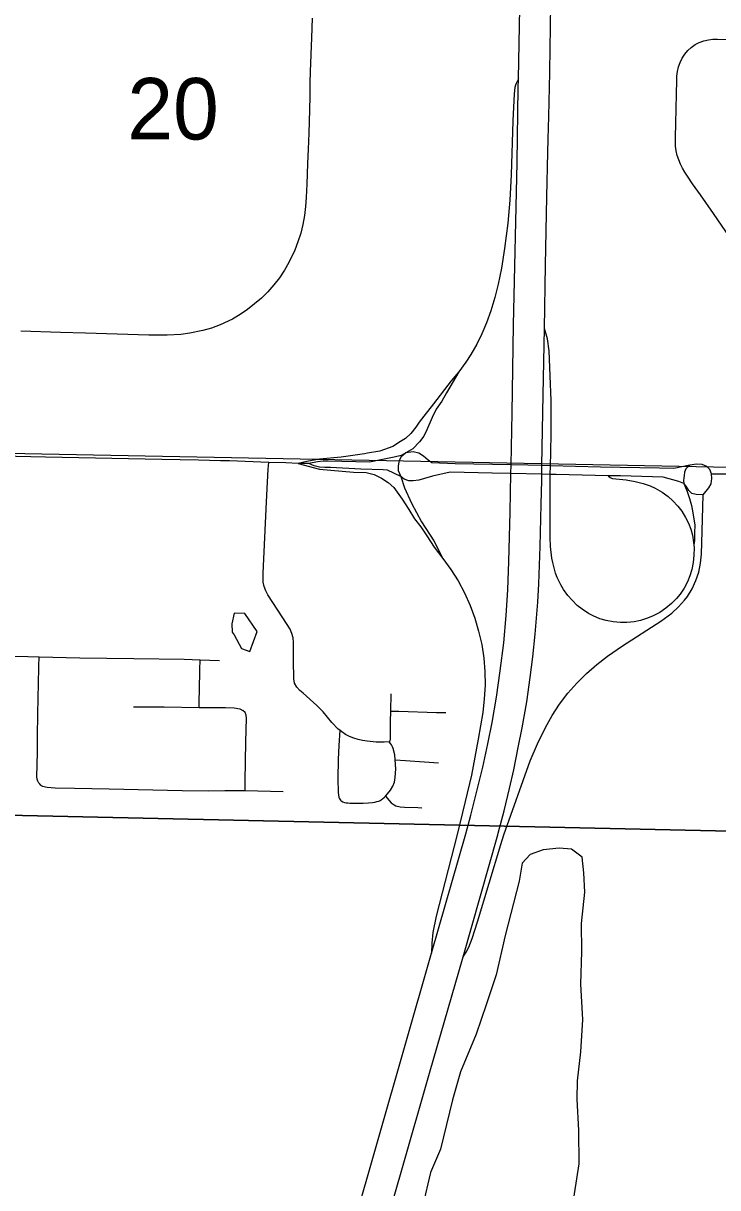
# Model space of a CAD drawing. Extents: x -59 to 43, y 0 to 22.
# Drawn here: x 26.628 to 27.1, y 17.014 to 17.807 of the extents above; entities that cross this region are included whole.
import ezdxf

# ---------------------------------------------------------------- set-up
doc = ezdxf.new("R2010")
doc.units = 0
for name, color, linetype in [('GM_X_City_Street', 7, 'Continuous'), ('GM_X_Interchange_Ramps', 7, 'Continuous'), ('GM_X_Interstate_Route', 7, 'Continuous'), ('GM_X_Minor_Lake', 7, 'Continuous'), ('GM_X_Rail_Line', 7, 'Continuous'), ('GM_X_Section', 7, 'Continuous'), ('GM_X_Section_Text', 7, 'Continuous'), ('GM_X_State_Route', 7, 'Continuous')]:
    doc.layers.add(name, color=color, linetype=linetype)

msp = doc.modelspace()

# ---------------------------------------------------------------- linework, layer by layer
at = {"layer": 'GM_X_City_Street'}
for p, q in [((26.87769, 17.33833), (26.87805, 17.34998)), ((26.77859, 17.28417), (26.80446, 17.28367))]:
    msp.add_line(p, q, dxfattribs=at)
for points in [[(26.82421, 17.81002), (26.82372, 17.79665), (26.82277, 17.77381), (26.82252, 17.76594), (26.82253, 17.75705), (26.82236, 17.74775), (26.82205, 17.73178), (26.82157, 17.72084), (26.82109, 17.71112), (26.82049, 17.69712), (26.82007, 17.68789), (26.81966, 17.68178), (26.81895, 17.67571), (26.81786, 17.66968), (26.8164, 17.66371), (26.81456, 17.65784), (26.81235, 17.65209), (26.80844, 17.64374), (26.80539, 17.63841), (26.80195, 17.6333), (26.7982, 17.62843), (26.79413, 17.62384), (26.78975, 17.61954), (26.78505, 17.61556), (26.78025, 17.61173), (26.77518, 17.60827), (26.76987, 17.60517), (26.76155, 17.6012), (26.75579, 17.59906), (26.74989, 17.59738), (26.74083, 17.59553), (26.73473, 17.59475), (26.7255, 17.59423), (26.71313, 17.59429), (26.66984, 17.59565), (26.65279, 17.59606), (26.62592, 17.59703)], [(27.12023, 17.64387), (27.09742, 17.67705), (27.08852, 17.68974), (27.08323, 17.69737), (27.07967, 17.70248), (27.07799, 17.70513), (27.07643, 17.70787), (27.07503, 17.71069), (27.07381, 17.7136), (27.07277, 17.7166), (27.07205, 17.71972), (27.07167, 17.72289), (27.07156, 17.72915), (27.07177, 17.73848), (27.07231, 17.75824), (27.07239, 17.76755), (27.07258, 17.77069), (27.073, 17.77383), (27.07372, 17.77694), (27.0748, 17.77995), (27.0762, 17.78282), (27.07791, 17.78553), (27.07994, 17.78802), (27.08229, 17.79021), (27.08493, 17.79206), (27.08778, 17.79353), (27.0908, 17.79465), (27.09393, 17.79536), (27.09708, 17.79572), (27.10022, 17.79584), (27.11882, 17.79547)], [(26.84297, 17.32526), (26.84197, 17.3261), (26.83771, 17.33061), (26.83168, 17.3377), (26.8274, 17.34218), (26.81815, 17.35045), (26.81592, 17.35236), (26.81374, 17.35454), (26.81226, 17.35723), (26.8117, 17.36025), (26.81152, 17.37267), (26.81146, 17.38508), (26.8112, 17.38817), (26.81046, 17.39116), (26.80921, 17.39398), (26.80427, 17.40187), (26.79411, 17.41747), (26.7926, 17.42019), (26.79149, 17.42307), (26.79096, 17.4261), (26.79088, 17.43231), (26.79311, 17.48072), (26.79385, 17.49426), (26.79435, 17.50299), (26.79477, 17.50758)], [(26.58492, 17.37613), (26.59661, 17.37603), (26.63063, 17.37539), (26.63829, 17.37522), (26.66608, 17.37458), (26.70277, 17.37405), (26.73697, 17.37363), (26.74792, 17.37324), (26.7612, 17.37277)], [(26.63811, 17.28919), (26.63745, 17.2905), (26.63701, 17.29206), (26.63686, 17.29357), (26.63713, 17.31038), (26.63731, 17.32096), (26.63739, 17.33654), (26.63819, 17.36769), (26.63821, 17.36893), (26.63829, 17.37522)], [(26.74728, 17.34081), (26.74739, 17.34562), (26.74756, 17.35245), (26.7478, 17.36643), (26.74792, 17.37324)], [(26.70251, 17.34121), (26.70917, 17.34117), (26.72355, 17.34125), (26.74728, 17.34081)], [(26.74728, 17.34081), (26.75566, 17.34066), (26.76533, 17.34069), (26.77117, 17.34045), (26.77488, 17.3398), (26.7771, 17.33865)], [(26.77859, 17.28417), (26.77869, 17.29065), (26.77908, 17.3174), (26.77943, 17.33355), (26.77924, 17.33544), (26.77858, 17.33725), (26.7771, 17.33865)], [(26.87663, 17.3174), (26.87725, 17.31815), (26.87763, 17.3192), (26.87748, 17.33132), (26.87769, 17.33833)], [(26.87769, 17.33833), (26.88323, 17.33816), (26.90879, 17.33742), (26.91519, 17.33739)], [(26.84297, 17.32526), (26.8424, 17.31486), (26.84189, 17.30529), (26.84166, 17.29244), (26.84198, 17.28287), (26.84217, 17.28122), (26.8424, 17.27977), (26.84267, 17.27902), (26.84297, 17.27826), (26.84344, 17.27759), (26.84392, 17.27711)], [(26.87663, 17.3174), (26.87331, 17.31708), (26.8677, 17.31721), (26.86165, 17.31787), (26.85859, 17.31836), (26.85557, 17.31906), (26.8526, 17.31995), (26.84969, 17.32103), (26.84692, 17.3224), (26.84434, 17.3241), (26.84297, 17.32526)], [(26.88082, 17.30511), (26.88044, 17.30845), (26.87943, 17.31274), (26.87901, 17.31397), (26.87822, 17.31538), (26.87753, 17.31635), (26.87663, 17.3174)], [(26.87423, 17.28048), (26.87561, 17.282), (26.87747, 17.28447), (26.87911, 17.2871), (26.8803, 17.28995), (26.88081, 17.29299), (26.88126, 17.29899), (26.88082, 17.30511)], [(26.88082, 17.30511), (26.88784, 17.30461), (26.91022, 17.30301)], [(26.63811, 17.28919), (26.63926, 17.28787), (26.64071, 17.28709), (26.64375, 17.28646), (26.64931, 17.28609), (26.66235, 17.28584), (26.68597, 17.28542), (26.71578, 17.28472), (26.73566, 17.28425), (26.75368, 17.28409), (26.76487, 17.28419), (26.77667, 17.2842), (26.77859, 17.28417)], [(26.84392, 17.27711), (26.84502, 17.27647), (26.84617, 17.27616), (26.84739, 17.2759), (26.84841, 17.27577), (26.84981, 17.2757), (26.859, 17.27572), (26.86246, 17.27587), (26.86519, 17.27613), (26.86687, 17.27641), (26.86823, 17.27669), (26.86953, 17.27704), (26.87043, 17.27743), (26.87108, 17.27784), (26.87243, 17.27882), (26.87353, 17.2797), (26.87423, 17.28048)], [(26.87423, 17.28048), (26.87668, 17.27753), (26.87811, 17.27578), (26.87994, 17.27453), (26.88117, 17.27387), (26.88406, 17.2732), (26.88704, 17.27291), (26.89608, 17.27274), (26.89897, 17.27251)]]:
    msp.add_lwpolyline(points, dxfattribs=at)
at = {"layer": 'GM_X_Interchange_Ramps'}
msp.add_line((26.82057, 17.50816), (26.81479, 17.50698), dxfattribs=at)
for points in [[(26.96464, 17.76877), (26.96302, 17.76572), (26.96264, 17.76451), (26.96227, 17.76288), (26.9618, 17.75863), (26.96082, 17.74008), (26.95977, 17.70344), (26.95875, 17.68607), (26.95734, 17.6706), (26.9552, 17.65333), (26.95302, 17.63984), (26.95079, 17.62888), (26.94854, 17.61983), (26.94585, 17.61091), (26.94293, 17.60272), (26.9398, 17.59528), (26.93622, 17.58805), (26.9322, 17.58105), (26.92882, 17.57584), (26.92404, 17.56933), (26.91889, 17.56312), (26.90684, 17.54744), (26.90017, 17.53918), (26.89713, 17.53493), (26.89482, 17.53153), (26.8913, 17.52741), (26.88766, 17.52401), (26.88438, 17.52194), (26.87904, 17.51842), (26.8703, 17.51539), (26.86194, 17.51383)], [(27.02583, 17.49858), (27.02703, 17.49738), (27.02796, 17.49692), (27.02879, 17.49666), (27.03806, 17.49568), (27.04419, 17.49466), (27.04962, 17.4933), (27.05429, 17.49162), (27.05769, 17.4901), (27.0625, 17.48727), (27.06652, 17.48435), (27.06977, 17.48146), (27.07316, 17.47784), (27.07578, 17.47436), (27.07839, 17.47013), (27.08033, 17.46623), (27.0819, 17.46218), (27.08311, 17.45801), (27.08393, 17.45311), (27.08406, 17.45157), (27.08424, 17.4494), (27.08416, 17.44442), (27.08364, 17.43948), (27.08263, 17.43461), (27.08138, 17.43044), (27.07974, 17.42641), (27.07747, 17.42199), (27.07468, 17.41789), (27.07234, 17.41498), (27.06881, 17.41148), (27.06498, 17.40831), (27.06086, 17.40552), (27.05648, 17.40319), (27.05246, 17.40151), (27.0477, 17.40006), (27.04344, 17.39918), (27.0385, 17.39863), (27.03414, 17.39858), (27.02919, 17.39899), (27.02432, 17.39995), (27.02015, 17.40118), (27.01558, 17.40313), (27.01228, 17.40486), (27.00813, 17.4076), (27.00473, 17.41031), (27.00115, 17.41376), (26.99831, 17.41705), (26.9954, 17.42109), (26.99351, 17.42429), (26.99108, 17.42932), (26.98995, 17.43221), (26.98798, 17.43939), (26.9874, 17.44242), (26.98657, 17.45048), (26.98629, 17.45665), (26.98624, 17.46602), (26.98632, 17.4994), (26.98648, 17.50531), (26.9868, 17.51442), (26.98704, 17.52743), (26.98688, 17.54978), (26.98617, 17.56651), (26.98557, 17.58351), (26.98435, 17.59168), (26.98232, 17.59883)], [(26.92404, 17.56933), (26.91563, 17.55497), (26.91243, 17.54936), (26.90856, 17.54389), (26.9059, 17.53816), (26.90229, 17.52989), (26.90029, 17.52549), (26.89722, 17.52162), (26.89269, 17.51684), (26.88793, 17.51411), (26.88453, 17.51112), (26.88348, 17.50875), (26.88322, 17.50771), (26.88269, 17.5052), (26.88274, 17.50214), (26.88458, 17.49795)], [(26.86194, 17.51383), (26.85986, 17.51344), (26.84395, 17.51126), (26.82926, 17.50992), (26.82057, 17.50816)], [(26.81479, 17.50698), (26.82925, 17.50294), (26.85234, 17.50107), (26.86107, 17.50072), (26.86649, 17.49944), (26.87152, 17.49687), (26.87601, 17.49396), (26.87976, 17.49061), (26.88548, 17.48267), (26.88992, 17.47547), (26.89396, 17.4693), (26.89812, 17.4638), (26.90223, 17.45763), (26.90725, 17.44985), (26.91311, 17.44222), (26.91862, 17.43477), (26.92358, 17.42692), (26.92795, 17.41873), (26.93173, 17.41026), (26.93493, 17.40154), (26.93756, 17.39264), (26.93962, 17.38359), (26.94107, 17.37442), (26.94185, 17.36517), (26.94194, 17.35589), (26.9414, 17.34663), (26.94031, 17.33741), (26.93731, 17.31908), (26.93259, 17.29477), (26.9284, 17.27669), (26.92286, 17.25436), (26.90873, 17.19869), (26.90648, 17.18749), (26.90561, 17.18033), (26.90551, 17.17359)], [(27.08122, 17.50571), (27.07851, 17.50317), (27.07765, 17.50106), (27.07737, 17.49879), (27.07717, 17.49703), (27.07708, 17.49542), (27.07728, 17.49337), (27.07952, 17.48782), (27.08108, 17.48314), (27.08244, 17.47827), (27.08342, 17.4734), (27.08481, 17.46493), (27.08462, 17.45985), (27.08446, 17.45435), (27.08406, 17.45157)], [(26.88458, 17.49795), (26.88708, 17.49031), (26.89185, 17.47978), (26.89859, 17.46711), (26.90705, 17.45434), (26.91311, 17.44222)]]:
    msp.add_lwpolyline(points, dxfattribs=at)
at = {"layer": 'GM_X_Interstate_Route'}
for points in [[(26.96464, 17.76877), (26.96855, 17.97347), (26.96886, 17.98963), (26.96974, 18.02444), (26.97068, 18.06983), (26.97222, 18.12888), (26.97341, 18.18049), (26.9738, 18.21595), (26.97395, 18.247), (26.97482, 18.28364), (26.97611, 18.35514), (26.97696, 18.39242), (26.97847, 18.45582), (26.97998, 18.54161), (26.98154, 18.62802), (26.98195, 18.65413), (26.98335, 18.72374), (26.98458, 18.78341), (26.98547, 18.82133), (26.98689, 18.89406), (26.98814, 18.95498), (26.98945, 19.03207)], [(26.9805, 17.49562), (26.98057, 17.49955), (26.98067, 17.50546), (26.98152, 17.55353), (26.98232, 17.59883), (26.98296, 17.64183), (26.98408, 17.68847), (26.98471, 17.71893), (26.98489, 17.72764), (26.98525, 17.74318), (26.98591, 17.77302), (26.98624, 17.78981), (26.98644, 17.80349), (26.98672, 17.82027)], [(26.8513, 16.98408), (26.90551, 17.17359), (26.92885, 17.25468), (26.93233, 17.26749), (26.93641, 17.28379), (26.94031, 17.30014), (26.94377, 17.31595), (26.94665, 17.33061), (26.94966, 17.34778), (26.95231, 17.36565), (26.95464, 17.38481), (26.95636, 17.40341), (26.95741, 17.42081), (26.95813, 17.44009), (26.95895, 17.47367), (26.95952, 17.50008), (26.95965, 17.50594), (26.96043, 17.54136), (26.96137, 17.60105), (26.96378, 17.71172), (26.96451, 17.76271), (26.96464, 17.76877)], [(26.95079, 17.2551), (26.95488, 17.27041), (26.95854, 17.2855), (26.96148, 17.2982), (26.96456, 17.31343), (26.96716, 17.32684), (26.97025, 17.34459), (26.9727, 17.36117), (26.97444, 17.37535), (26.97609, 17.39079), (26.97779, 17.41247), (26.97852, 17.42487), (26.97953, 17.45033), (26.98021, 17.47892), (26.9805, 17.49562)], [(26.80488, 16.7469), (26.80603, 16.75068), (26.80832, 16.75821), (26.81613, 16.78392), (26.82413, 16.8107), (26.83584, 16.85261), (26.84824, 16.89756), (26.88522, 17.02601), (26.90421, 17.09172), (26.92694, 17.17102), (26.95053, 17.25414), (26.95079, 17.2551)]]:
    msp.add_lwpolyline(points, dxfattribs=at)
at = {"layer": 'GM_X_Minor_Lake'}
for p, q in [((26.76974, 17.39209), (26.77123, 17.39017)), ((26.91982, 17.07372), (26.91161, 17.04006))]:
    msp.add_line(p, q, dxfattribs=at)
for points in [[(26.77123, 17.39017), (26.776, 17.38096), (26.78167, 17.37896), (26.78685, 17.39255), (26.77833, 17.40486), (26.77111, 17.40499), (26.76946, 17.3978), (26.76974, 17.39209)], [(27.00133, 16.99932), (27.00606, 17.03001), (27.00571, 17.05281), (27.00458, 17.0741), (27.0048, 17.08664), (27.00706, 17.10635), (27.00859, 17.12835), (27.00712, 17.15232), (27.00791, 17.17471), (27.00749, 17.19372), (27.00977, 17.21495), (27.00925, 17.22825), (27.00792, 17.23891), (27.0008, 17.24436), (26.99245, 17.24489), (26.98141, 17.24395), (26.97261, 17.24069), (26.96718, 17.23471), (26.96506, 17.22259), (26.95566, 17.18553), (26.94947, 17.15866), (26.94264, 17.13827), (26.93582, 17.11826), (26.9251, 17.09262), (26.91982, 17.07372)], [(26.91161, 17.04006), (26.90487, 17.02422), (26.89953, 17.0019)]]:
    msp.add_lwpolyline(points, dxfattribs=at)
at = {"layer": 'GM_X_Rail_Line'}
msp.add_lwpolyline([(25.49709, 17.54189), (25.77492, 17.52887), (26.01785, 17.52436), (26.26566, 17.51811), (26.51107, 17.51606), (27.27325, 17.50116)], dxfattribs=at)
at = {"layer": 'GM_X_Section'}
for points in [[(26.26587, 18.27048), (27.29175, 18.24494), (27.27299, 17.25298), (26.27822, 17.27501)], [(27.27299, 17.25298), (27.23736, 16.24538), (26.23614, 16.26224), (26.27822, 17.27501)]]:
    msp.add_lwpolyline(points, close=True, dxfattribs=at)
at = {"layer": 'GM_X_State_Route'}
msp.add_line((27.09613, 17.49988), (27.11887, 17.49973), dxfattribs=at)
for points in [[(26.82187, 17.50677), (26.81479, 17.50698), (26.80619, 17.50724), (26.79477, 17.50758), (26.7679, 17.50859), (26.76188, 17.50881), (26.74678, 17.5091), (26.72191, 17.50959), (26.64259, 17.51126), (26.61282, 17.5118), (26.58428, 17.51227), (26.55517, 17.51289), (26.51624, 17.51391), (26.47814, 17.51431), (26.4288, 17.51553), (26.37968, 17.51635), (26.32327, 17.51757), (26.29745, 17.51798), (26.27885, 17.5183), (26.26232, 17.51846), (26.21865, 17.51928), (26.1729, 17.52014), (26.1486, 17.52059), (26.13865, 17.52078)], [(26.90579, 17.50723), (26.90309, 17.50906), (26.90011, 17.51177), (26.89686, 17.51384), (26.89298, 17.51484), (26.88793, 17.51411), (26.88477, 17.51222), (26.88005, 17.51111), (26.87214, 17.50969), (26.86325, 17.50782)], [(26.86325, 17.50782), (26.83501, 17.50848), (26.83173, 17.50837), (26.82781, 17.50794), (26.82187, 17.50677)], [(26.87248, 17.5025), (26.85743, 17.50303), (26.83661, 17.50406), (26.83289, 17.50413), (26.82929, 17.50444), (26.82558, 17.50529), (26.82187, 17.50677)], [(27.07049, 17.50338), (27.0607, 17.50365), (27.02053, 17.50447), (26.98648, 17.50531), (26.98067, 17.50546), (26.9711, 17.50569), (26.95965, 17.50594), (26.92166, 17.50676), (26.90579, 17.50723)], [(27.09613, 17.49988), (27.09501, 17.5028), (27.09292, 17.50487), (27.08964, 17.50617), (27.08597, 17.50633), (27.08122, 17.50571), (27.07049, 17.50338)], [(27.07777, 17.49272), (27.07728, 17.49337), (27.07387, 17.49464), (27.06325, 17.49747), (27.03415, 17.49841), (27.02583, 17.49858), (26.99039, 17.49929), (26.98632, 17.4994), (26.98057, 17.49955), (26.95952, 17.50008), (26.94665, 17.50041), (26.91823, 17.50105), (26.90605, 17.49815), (26.90065, 17.49664), (26.8969, 17.49558), (26.89308, 17.49499), (26.89011, 17.49512), (26.88689, 17.49631), (26.88458, 17.49795), (26.8755, 17.50239), (26.87248, 17.5025)], [(27.09046, 17.48551), (27.09424, 17.49024), (27.09593, 17.49315), (27.09639, 17.49667), (27.09613, 17.49988)], [(27.09046, 17.48551), (27.08557, 17.48568), (27.08264, 17.48655), (27.08059, 17.4885), (27.07874, 17.49142), (27.07777, 17.49272)], [(26.92694, 17.17102), (26.92914, 17.17418), (26.93092, 17.17755), (26.93314, 17.18344), (26.93684, 17.19479), (26.95256, 17.24752), (26.95463, 17.25402), (26.97271, 17.30453), (26.97757, 17.31593), (26.98297, 17.32708), (26.98752, 17.3352), (26.99257, 17.34299), (26.99817, 17.35041), (27.00432, 17.35737), (27.01094, 17.36389), (27.01797, 17.36997), (27.02534, 17.37562), (27.03556, 17.38263), (27.06156, 17.39953), (27.06904, 17.40505), (27.07364, 17.40919), (27.07778, 17.41379), (27.07964, 17.41625), (27.08291, 17.4215), (27.08551, 17.42711), (27.08737, 17.433), (27.08855, 17.43907), (27.08921, 17.44523), (27.08982, 17.46072), (27.09046, 17.48551)]]:
    msp.add_lwpolyline(points, dxfattribs=at)

# ---------------------------------------------------------------- texts
at = {"layer": 'GM_X_Section_Text'}
msp.add_text('20', height=0.041856, rotation=0.00001, dxfattribs=at).set_placement((26.69839, 17.72749))

doc.saveas('drawing.dxf')
